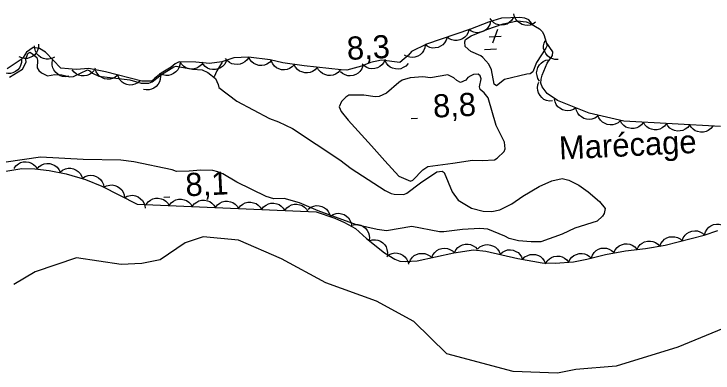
# Model space of a CAD drawing. Extents: x 336540 to 340074, y 5572036 to 5573747.
# Drawn here: x 336751.6 to 336842.2, y 5573514.1 to 5573560.7 of the extents above; entities that cross this region are included whole.
import ezdxf

# ---------------------------------------------------------------- set-up
doc = ezdxf.new("R2010")
doc.units = 0
for name, color, linetype in [('Niveau 2', 7, 'Continuous'), ('Niveau 3', 7, 'Continuous'), ('Niveau 4', 7, 'Continuous'), ('Niveau 44', 7, 'Continuous'), ('Niveau 7', 7, 'Continuous')]:
    doc.layers.add(name, color=color, linetype=linetype)

msp = doc.modelspace()

# ---------------------------------------------------------------- linework, layer by layer
at = {"layer": 'Niveau 2'}
msp.add_lwpolyline([(336844.29, 5573520.18), (336837.67, 5573517.45), (336829.68, 5573514.99), (336824.44, 5573514.55), (336822.1, 5573514.1), (336816.33, 5573514.3), (336807.75, 5573516.58), (336803.46, 5573520.78), (336798.6, 5573523.41), (336792.05, 5573525.78), (336786.31, 5573528.9), (336780.75, 5573531.32), (336776.16, 5573531.76), (336773.82, 5573530.97), (336770.56, 5573528.77), (336768.22, 5573528.3), (336765.51, 5573528.16), (336759.71, 5573529.05), (336754.39, 5573527.24), (336751.62, 5573525.57)], dxfattribs=at)
at = {"layer": 'Niveau 3'}
for p, q in [((336814.31, 5573558.66), (336813.66, 5573556.86)), ((336813.22, 5573557.7), (336814.78, 5573557.78)), ((336812.6, 5573556.07), (336814.19, 5573556.15)), ((336803.13, 5573547.11), (336803.93, 5573547.15)), ((336771.04, 5573536.91), (336771.84, 5573536.95))]:
    msp.add_line(p, q, dxfattribs=at)
at = {"layer": 'Niveau 4'}
for points in [[(336815.2, 5573552.15), (336814.19, 5573551.34), (336813.86, 5573551.56), (336813.54, 5573553.42), (336813.19, 5573554.14), (336812.42, 5573555.02), (336812.13, 5573555.23), (336810.87, 5573555.8), (336810.12, 5573556.44), (336810.05, 5573557.04), (336810.15, 5573557.33), (336810.9, 5573557.82), (336812.91, 5573558.65), (336815.05, 5573559.4), (336816.88, 5573559.76), (336818.03, 5573559.66), (336818.5, 5573559.48), (336819.77, 5573558.74), (336820.08, 5573558.37), (336820.3, 5573557.98), (336820.73, 5573556.56), (336820.59, 5573556.24), (336819.36, 5573554.38), (336818.9, 5573553.15), (336818.55, 5573552.88), (336818.1, 5573552.86), (336815.2, 5573552.15)], [(336751.05, 5573552.48), (336752.75, 5573553.49), (336753.19, 5573554.43), (336753.18, 5573554.78), (336753.4, 5573555.53), (336753.68, 5573555.69), (336754.03, 5573555.51), (336754.59, 5573555.02), (336754.68, 5573554.66), (336754.63, 5573553.68), (336754.86, 5573553.35), (336755.2, 5573553.02), (336755.99, 5573552.63), (336756.91, 5573552.83), (336757.84, 5573552.77), (336758.88, 5573552.49), (336759.36, 5573552.56), (336761.15, 5573553.42), (336761.47, 5573553.28), (336761.82, 5573552.97), (336762.61, 5573552.58), (336766.65, 5573552.1), (336768.12, 5573551.67), (336769.11, 5573551.67), (336769.53, 5573551.87), (336770.75, 5573552.79), (336772.35, 5573553.79), (336772.66, 5573553.88), (336774.77, 5573553.52), (336776.02, 5573553.42), (336776.77, 5573553.06), (336777.75, 5573552.3), (336778.1, 5573551.51), (336778.16, 5573551.11), (336780.53, 5573549.35), (336784.73, 5573547.09), (336785.93, 5573546.67), (336787.73, 5573545.81), (336793.87, 5573541.76), (336795.34, 5573540.62), (336799.75, 5573537.77), (336800.53, 5573537.4), (336800.89, 5573537.31), (336802.15, 5573537.26), (336802.56, 5573537.42), (336804.33, 5573538.76), (336806.42, 5573540.2), (336807.14, 5573540.29), (336807.38, 5573540.1), (336808.42, 5573537.61), (336809.2, 5573536.51), (336810.93, 5573535.47), (336812.43, 5573535.07), (336813.57, 5573535.04), (336814.6, 5573535.28), (336816.16, 5573536.04), (336817.61, 5573537.02), (336819.72, 5573538.28), (336821.34, 5573539.01), (336822.69, 5573539.31), (336823.55, 5573539.09), (336824.86, 5573538.46), (336826.07, 5573537.59), (336827.55, 5573536.36), (336828.25, 5573535.45)], [(336828.25, 5573535.45), (336828.13, 5573534.78), (336827.9, 5573534.43), (336827.21, 5573533.81), (336824.31, 5573532.89), (336822.67, 5573532.11), (336819.92, 5573531.12), (336818.65, 5573531.11), (336817.01, 5573531.26), (336815.81, 5573531.54), (336815.26, 5573531.84), (336813.04, 5573532.77), (336812, 5573532.82), (336809.76, 5573532.72), (336807.37, 5573532.41), (336806.78, 5573532.4), (336803.2, 5573533.11), (336799.93, 5573532.54), (336798.72, 5573532.73), (336796.04, 5573533.33), (336791.04, 5573535.13), (336788.62, 5573536.16), (336786.67, 5573536.72), (336785.31, 5573536.71), (336784.3, 5573536.99), (336780.5, 5573538.85), (336778.69, 5573539.93), (336778.07, 5573540.21), (336777.39, 5573540.37), (336775.85, 5573540.42), (336774.35, 5573540.26), (336772.7, 5573540.25), (336772.12, 5573540.44), (336767.17, 5573541.5), (336765.48, 5573541.69), (336760.58, 5573541.8), (336755.06, 5573542.1), (336750.61, 5573541.46)]]:
    msp.add_lwpolyline(points, dxfattribs=at)
at = {"layer": 'Niveau 44'}
for points in [[(336819.25, 5573559.59), (336818.9, 5573559.35), (336818.52, 5573559.22), (336818.19, 5573559.16), (336817.84, 5573559.2), (336817.49, 5573559.3), (336817.16, 5573559.5), (336816.89, 5573559.69), (336816.69, 5573559.98), (336816.53, 5573560.31), (336816.44, 5573560.66)], [(336818.95, 5573559.19), (336818.38, 5573559.92), (336817.83, 5573560.13), (336817.2, 5573560.19), (336814.82, 5573560.11), (336813.12, 5573559.61), (336810.81, 5573558.71), (336805.11, 5573556.76), (336803.17, 5573555.79), (336802.79, 5573555.33), (336801.65, 5573554.36), (336799.26, 5573554.66), (336797.84, 5573554.38), (336796.66, 5573553.89), (336794.79, 5573553.39), (336794.03, 5573553.4), (336789.24, 5573553.94), (336786.47, 5573554.31), (336784.83, 5573554.7), (336782.02, 5573555.08), (336780.13, 5573554.96), (336778.59, 5573554.47), (336776.95, 5573554.24), (336775.18, 5573554.41), (336773.06, 5573554.45), (336772.53, 5573554.2), (336771.99, 5573553.77), (336770.725, 5573552.987), (336769.821, 5573552.287), (336769.46, 5573551.93), (336768.19, 5573551.93), (336763.47, 5573553.16), (336761.35, 5573553.58), (336759.69, 5573553.44), (336757.72, 5573553.65), (336755.731, 5573555.712), (336754.935, 5573556.163)], [(336813.4, 5573559.72), (336813.31, 5573559.31), (336813.11, 5573558.96), (336812.91, 5573558.7), (336812.62, 5573558.49), (336812.29, 5573558.33), (336811.92, 5573558.25), (336811.59, 5573558.22), (336811.25, 5573558.29), (336810.9, 5573558.43), (336810.61, 5573558.63)], [(336816.35, 5573560.16), (336816.13, 5573559.81), (336815.82, 5573559.54), (336815.54, 5573559.36), (336815.21, 5573559.26), (336814.84, 5573559.21), (336814.46, 5573559.27), (336814.14, 5573559.34), (336813.84, 5573559.53), (336813.56, 5573559.77), (336813.35, 5573560.06)], [(336810.6, 5573558.64), (336810.49, 5573558.24), (336810.28, 5573557.89), (336810.07, 5573557.64), (336809.77, 5573557.44), (336809.43, 5573557.29), (336809.06, 5573557.23), (336808.73, 5573557.21), (336808.39, 5573557.3), (336808.05, 5573557.45), (336807.76, 5573557.67)], [(336807.76, 5573557.67), (336807.65, 5573557.26), (336807.44, 5573556.92), (336807.23, 5573556.67), (336806.93, 5573556.47), (336806.6, 5573556.32), (336806.22, 5573556.26), (336805.89, 5573556.24), (336805.55, 5573556.33), (336805.21, 5573556.48), (336804.93, 5573556.7)], [(336843.22, 5573546.08), (336830.69, 5573546.74), (336826.18, 5573547.81), (336822.07, 5573549.46), (336820.75, 5573550.33), (336820.11, 5573551.2), (336819.94, 5573551.7), (336819.96, 5573552.2), (336820.09, 5573552.72), (336820.74, 5573554.26), (336821.43, 5573555.27), (336821.49, 5573555.75), (336820.63, 5573557)], [(336822.17, 5573554.76), (336821.75, 5573554.75), (336821.36, 5573554.87), (336821.06, 5573555), (336820.8, 5573555.23), (336820.56, 5573555.52), (336820.4, 5573555.87), (336820.29, 5573556.17), (336820.29, 5573556.53), (336820.34, 5573556.89), (336820.47, 5573557.23)], [(336754.935, 5573556.163), (336754.13, 5573556.3), (336753.25, 5573555.72), (336752.82, 5573555.02), (336752.43, 5573554.66), (336750.76, 5573553.55)], [(336754.81, 5573556.75), (336754.81, 5573556.33), (336754.68, 5573555.94), (336754.54, 5573555.65), (336754.31, 5573555.38), (336754.02, 5573555.15), (336753.67, 5573555), (336753.36, 5573554.9), (336753.01, 5573554.9), (336752.64, 5573554.96), (336752.31, 5573555.1)], [(336756.89, 5573555.05), (336756.52, 5573554.87), (336756.12, 5573554.8), (336755.79, 5573554.79), (336755.45, 5573554.88), (336755.11, 5573555.03), (336754.81, 5573555.28), (336754.58, 5573555.51), (336754.42, 5573555.82), (336754.31, 5573556.18), (336754.28, 5573556.53)], [(336804.94, 5573556.67), (336804.88, 5573556.26), (336804.71, 5573555.89), (336804.54, 5573555.61), (336804.27, 5573555.38), (336803.96, 5573555.18), (336803.59, 5573555.07), (336803.27, 5573555.01), (336802.92, 5573555.05), (336802.57, 5573555.15), (336802.25, 5573555.33)], [(336782.05, 5573555.08), (336781.84, 5573554.72), (336781.54, 5573554.45), (336781.27, 5573554.26), (336780.94, 5573554.15), (336780.57, 5573554.09), (336780.19, 5573554.13), (336779.87, 5573554.2), (336779.57, 5573554.37), (336779.28, 5573554.61), (336779.06, 5573554.89)], [(336785.03, 5573554.67), (336784.75, 5573554.36), (336784.4, 5573554.15), (336784.1, 5573554.02), (336783.75, 5573553.97), (336783.38, 5573553.99), (336783.01, 5573554.11), (336782.71, 5573554.24), (336782.45, 5573554.47), (336782.21, 5573554.75), (336782.05, 5573555.08)], [(336752.62, 5573554.78), (336752.61, 5573554.37), (336752.49, 5573553.98), (336752.35, 5573553.68), (336752.12, 5573553.42), (336751.83, 5573553.18), (336751.48, 5573553.03), (336751.17, 5573552.93), (336750.82, 5573552.93), (336750.45, 5573552.99), (336750.12, 5573553.12)], [(336758.74, 5573552.59), (336758.33, 5573552.52), (336757.92, 5573552.57), (336757.6, 5573552.65), (336757.3, 5573552.84), (336757.03, 5573553.08), (336756.81, 5573553.4), (336756.65, 5573553.68), (336756.59, 5573554.03), (336756.58, 5573554.4), (336756.66, 5573554.75)], [(336773.16, 5573554.49), (336773.14, 5573554.08), (336773.01, 5573553.69), (336772.86, 5573553.4), (336772.62, 5573553.14), (336772.32, 5573552.92), (336771.96, 5573552.78), (336771.65, 5573552.69), (336771.3, 5573552.7), (336770.94, 5573552.77), (336770.61, 5573552.91)], [(336776.16, 5573554.39), (336775.92, 5573554.05), (336775.6, 5573553.8), (336775.31, 5573553.63), (336774.97, 5573553.55), (336774.6, 5573553.52), (336774.22, 5573553.6), (336773.91, 5573553.69), (336773.62, 5573553.89), (336773.35, 5573554.15), (336773.16, 5573554.45)], [(336779.13, 5573554.55), (336778.94, 5573554.17), (336778.67, 5573553.87), (336778.41, 5573553.66), (336778.09, 5573553.53), (336777.73, 5573553.44), (336777.34, 5573553.46), (336777.02, 5573553.5), (336776.7, 5573553.65), (336776.4, 5573553.86), (336776.16, 5573554.13)], [(336787.97, 5573554.11), (336787.69, 5573553.8), (336787.34, 5573553.59), (336787.04, 5573553.45), (336786.69, 5573553.41), (336786.32, 5573553.43), (336785.96, 5573553.54), (336785.66, 5573553.67), (336785.39, 5573553.9), (336785.16, 5573554.18), (336784.99, 5573554.51)], [(336799.73, 5573554.75), (336799.56, 5573554.37), (336799.3, 5573554.06), (336799.06, 5573553.83), (336798.74, 5573553.68), (336798.39, 5573553.58), (336798.01, 5573553.56), (336797.68, 5573553.59), (336797.35, 5573553.72), (336797.04, 5573553.92), (336796.78, 5573554.17)], [(336802.71, 5573554.23), (336802.43, 5573553.91), (336802.09, 5573553.7), (336801.79, 5573553.56), (336801.44, 5573553.52), (336801.07, 5573553.53), (336800.7, 5573553.64), (336800.4, 5573553.77), (336800.13, 5573554), (336799.9, 5573554.28), (336799.73, 5573554.6)], [(336819.77, 5573551.96), (336819.54, 5573552.31), (336819.43, 5573552.7), (336819.38, 5573553.03), (336819.43, 5573553.37), (336819.54, 5573553.73), (336819.75, 5573554.05), (336819.95, 5573554.3), (336820.24, 5573554.5), (336820.58, 5573554.65), (336820.94, 5573554.72)], [(336762.17, 5573553.65), (336761.96, 5573553.28), (336761.67, 5573553), (336761.4, 5573552.81), (336761.07, 5573552.69), (336760.71, 5573552.63), (336760.33, 5573552.66), (336760.01, 5573552.72), (336759.7, 5573552.89), (336759.41, 5573553.12), (336759.18, 5573553.4)], [(336765.08, 5573552.74), (336764.76, 5573552.47), (336764.39, 5573552.3), (336764.08, 5573552.2), (336763.72, 5573552.2), (336763.36, 5573552.26), (336763.01, 5573552.42), (336762.73, 5573552.58), (336762.49, 5573552.85), (336762.29, 5573553.16), (336762.17, 5573553.5)], [(336790.95, 5573553.75), (336790.67, 5573553.43), (336790.33, 5573553.21), (336790.03, 5573553.07), (336789.68, 5573553.02), (336789.32, 5573553.03), (336788.95, 5573553.14), (336788.64, 5573553.26), (336788.37, 5573553.48), (336788.13, 5573553.76), (336787.96, 5573554.08)], [(336793.93, 5573553.41), (336793.66, 5573553.09), (336793.31, 5573552.87), (336793.01, 5573552.74), (336792.67, 5573552.68), (336792.3, 5573552.69), (336791.93, 5573552.8), (336791.63, 5573552.92), (336791.36, 5573553.15), (336791.11, 5573553.43), (336790.95, 5573553.75)], [(336796.85, 5573553.94), (336796.72, 5573553.55), (336796.48, 5573553.22), (336796.25, 5573552.98), (336795.94, 5573552.8), (336795.6, 5573552.68), (336795.22, 5573552.64), (336794.89, 5573552.65), (336794.56, 5573552.76), (336794.23, 5573552.93), (336793.96, 5573553.17)], [(336767.98, 5573551.98), (336767.67, 5573551.71), (336767.3, 5573551.54), (336766.98, 5573551.45), (336766.63, 5573551.44), (336766.26, 5573551.51), (336765.91, 5573551.66), (336765.63, 5573551.83), (336765.4, 5573552.09), (336765.2, 5573552.4), (336765.08, 5573552.74)], [(336770.54, 5573552.99), (336770.61, 5573552.58), (336770.57, 5573552.18), (336770.49, 5573551.86), (336770.31, 5573551.56), (336770.07, 5573551.27), (336769.76, 5573551.05), (336769.47, 5573550.9), (336769.13, 5573550.83), (336768.76, 5573550.81), (336768.4, 5573550.88)], [(336821.45, 5573549.38), (336821.03, 5573549.36), (336820.64, 5573549.46), (336820.33, 5573549.59), (336820.06, 5573549.81), (336819.82, 5573550.09), (336819.64, 5573550.43), (336819.53, 5573550.74), (336819.51, 5573551.09), (336819.55, 5573551.46), (336819.67, 5573551.8)], [(336824.48, 5573548.49), (336824.14, 5573548.26), (336823.75, 5573548.14), (336823.42, 5573548.08), (336823.07, 5573548.13), (336822.72, 5573548.23), (336822.39, 5573548.43), (336822.13, 5573548.63), (336821.93, 5573548.92), (336821.78, 5573549.26), (336821.7, 5573549.61)], [(336827.27, 5573547.37), (336826.92, 5573547.14), (336826.53, 5573547.02), (336826.21, 5573546.97), (336825.86, 5573547.01), (336825.5, 5573547.12), (336825.18, 5573547.32), (336824.92, 5573547.51), (336824.72, 5573547.8), (336824.56, 5573548.14), (336824.48, 5573548.49)], [(336830.24, 5573546.85), (336829.93, 5573546.56), (336829.56, 5573546.39), (336829.25, 5573546.29), (336828.9, 5573546.28), (336828.53, 5573546.33), (336828.18, 5573546.48), (336827.9, 5573546.64), (336827.65, 5573546.9), (336827.45, 5573547.2), (336827.32, 5573547.54)], [(336833.22, 5573546.61), (336832.97, 5573546.27), (336832.64, 5573546.03), (336832.35, 5573545.88), (336832.01, 5573545.81), (336831.64, 5573545.79), (336831.26, 5573545.88), (336830.95, 5573545.98), (336830.67, 5573546.19), (336830.41, 5573546.46), (336830.23, 5573546.76)], [(336836.22, 5573546.45), (336835.97, 5573546.12), (336835.64, 5573545.88), (336835.35, 5573545.72), (336835, 5573545.65), (336834.63, 5573545.64), (336834.26, 5573545.72), (336833.95, 5573545.82), (336833.67, 5573546.03), (336833.41, 5573546.3), (336833.22, 5573546.61)], [(336839.21, 5573546.29), (336838.96, 5573545.96), (336838.63, 5573545.72), (336838.34, 5573545.56), (336838, 5573545.49), (336837.63, 5573545.48), (336837.26, 5573545.56), (336836.95, 5573545.67), (336836.66, 5573545.87), (336836.4, 5573546.14), (336836.22, 5573546.45)], [(336842.21, 5573546.13), (336841.96, 5573545.8), (336841.63, 5573545.56), (336841.34, 5573545.4), (336840.99, 5573545.33), (336840.63, 5573545.32), (336840.25, 5573545.4), (336839.94, 5573545.51), (336839.66, 5573545.72), (336839.4, 5573545.98), (336839.21, 5573546.29)], [(336751.64, 5573540.63), (336751.88, 5573540.97), (336752.2, 5573541.22), (336752.48, 5573541.39), (336752.83, 5573541.47), (336753.19, 5573541.5), (336753.57, 5573541.43), (336753.88, 5573541.33), (336754.17, 5573541.13), (336754.44, 5573540.88), (336754.64, 5573540.57)], [(336750.33, 5573540.25), (336752.63, 5573540.61), (336754.34, 5573540.58), (336756.2, 5573540.36), (336758.41, 5573539.92), (336760.89, 5573539.21), (336763.02, 5573538.31), (336767.6, 5573536)], [(336754.64, 5573540.54), (336754.91, 5573540.86), (336755.25, 5573541.08), (336755.55, 5573541.22), (336755.9, 5573541.27), (336756.27, 5573541.25), (336756.64, 5573541.15), (336756.94, 5573541.02), (336757.21, 5573540.79), (336757.45, 5573540.51), (336757.62, 5573540.19)], [(336757.61, 5573540.15), (336757.93, 5573540.42), (336758.31, 5573540.58), (336758.63, 5573540.66), (336758.98, 5573540.66), (336759.34, 5573540.59), (336759.69, 5573540.42), (336759.96, 5573540.25), (336760.19, 5573539.98), (336760.39, 5573539.66), (336760.5, 5573539.32)], [(336760.51, 5573539.37), (336760.86, 5573539.6), (336761.26, 5573539.71), (336761.58, 5573539.76), (336761.93, 5573539.71), (336762.28, 5573539.59), (336762.6, 5573539.39), (336762.86, 5573539.19), (336763.06, 5573538.89), (336763.21, 5573538.55), (336763.28, 5573538.2)], [(336763.27, 5573538.18), (336763.63, 5573538.39), (336764.03, 5573538.47), (336764.36, 5573538.5), (336764.71, 5573538.43), (336765.05, 5573538.29), (336765.36, 5573538.06), (336765.6, 5573537.84), (336765.77, 5573537.54), (336765.9, 5573537.19), (336765.95, 5573536.83)], [(336765.95, 5573536.83), (336766.31, 5573537.04), (336766.71, 5573537.12), (336767.04, 5573537.15), (336767.38, 5573537.08), (336767.73, 5573536.94), (336768.04, 5573536.71), (336768.28, 5573536.49), (336768.45, 5573536.19), (336768.58, 5573535.84), (336768.63, 5573535.48)], [(336767.6, 5573536), (336790.786, 5573535.001), (336793.231, 5573534.185), (336794.479, 5573533.637), (336795.89, 5573532.86), (336797.31, 5573531.54), (336799.65, 5573529.68), (336800.99, 5573528.86), (336801.66, 5573528.62), (336802.38, 5573528.55), (336803.91, 5573528.63), (336808.63, 5573529.67), (336811.19, 5573530.06), (336812.81, 5573529.92), (336816.95, 5573528.97), (336820.11, 5573528.39), (336821.79, 5573528.36), (336824.14, 5573528.54), (336825.87, 5573528.85), (336828.31, 5573529.49), (336830.88, 5573529.95), (336833.49, 5573530.25), (336836.04, 5573530.68), (336841.1, 5573531.98), (336842.85, 5573532.57)], [(336768.75, 5573535.95), (336769, 5573536.29), (336769.32, 5573536.53), (336769.61, 5573536.69), (336769.96, 5573536.76), (336770.33, 5573536.78), (336770.7, 5573536.7), (336771.01, 5573536.6), (336771.3, 5573536.39), (336771.56, 5573536.13), (336771.75, 5573535.82)], [(336771.75, 5573535.82), (336772, 5573536.16), (336772.32, 5573536.4), (336772.61, 5573536.56), (336772.95, 5573536.63), (336773.32, 5573536.65), (336773.7, 5573536.57), (336774.01, 5573536.47), (336774.29, 5573536.26), (336774.55, 5573536), (336774.74, 5573535.69)], [(336774.74, 5573535.69), (336774.99, 5573536.03), (336775.32, 5573536.27), (336775.61, 5573536.43), (336775.95, 5573536.5), (336776.32, 5573536.52), (336776.7, 5573536.44), (336777.01, 5573536.34), (336777.29, 5573536.13), (336777.55, 5573535.87), (336777.74, 5573535.56)], [(336777.74, 5573535.56), (336777.99, 5573535.9), (336778.32, 5573536.14), (336778.61, 5573536.3), (336778.95, 5573536.38), (336779.32, 5573536.39), (336779.69, 5573536.31), (336780, 5573536.21), (336780.29, 5573536), (336780.55, 5573535.74), (336780.74, 5573535.43)], [(336780.74, 5573535.43), (336780.99, 5573535.77), (336781.31, 5573536.01), (336781.6, 5573536.17), (336781.95, 5573536.25), (336782.32, 5573536.26), (336782.69, 5573536.18), (336783, 5573536.08), (336783.29, 5573535.87), (336783.55, 5573535.61), (336783.74, 5573535.3)], [(336783.74, 5573535.3), (336783.98, 5573535.64), (336784.31, 5573535.88), (336784.6, 5573536.04), (336784.94, 5573536.12), (336785.31, 5573536.13), (336785.69, 5573536.05), (336786, 5573535.95), (336786.28, 5573535.75), (336786.54, 5573535.48), (336786.73, 5573535.18)], [(336786.73, 5573535.18), (336786.98, 5573535.51), (336787.31, 5573535.75), (336787.6, 5573535.91), (336787.94, 5573535.99), (336788.31, 5573536), (336788.68, 5573535.92), (336788.99, 5573535.82), (336789.28, 5573535.62), (336789.54, 5573535.35), (336789.73, 5573535.05)], [(336789.78, 5573535.34), (336790.11, 5573535.59), (336790.5, 5573535.73), (336790.82, 5573535.81), (336791.17, 5573535.78), (336791.53, 5573535.7), (336791.87, 5573535.52), (336792.14, 5573535.33), (336792.35, 5573535.06), (336792.53, 5573534.73), (336792.63, 5573534.39)], [(336792.65, 5573534.44), (336793, 5573534.66), (336793.4, 5573534.77), (336793.72, 5573534.81), (336794.07, 5573534.76), (336794.42, 5573534.64), (336794.74, 5573534.43), (336794.99, 5573534.22), (336795.18, 5573533.93), (336795.33, 5573533.59), (336795.4, 5573533.23)], [(336795.44, 5573533.27), (336795.85, 5573533.37), (336796.26, 5573533.34), (336796.58, 5573533.27), (336796.89, 5573533.11), (336797.18, 5573532.88), (336797.42, 5573532.58), (336797.59, 5573532.3), (336797.67, 5573531.96), (336797.7, 5573531.59), (336797.64, 5573531.23)], [(336841.15, 5573532), (336841.26, 5573532.4), (336841.48, 5573532.74), (336841.69, 5573533), (336841.98, 5573533.19), (336842.32, 5573533.34), (336842.7, 5573533.4), (336843.03, 5573533.41), (336843.37, 5573533.32), (336843.7, 5573533.17), (336843.99, 5573532.95)], [(336838.24, 5573531.25), (336838.38, 5573531.64), (336838.63, 5573531.97), (336838.86, 5573532.2), (336839.16, 5573532.37), (336839.51, 5573532.5), (336839.89, 5573532.53), (336840.22, 5573532.52), (336840.55, 5573532.41), (336840.88, 5573532.23), (336841.15, 5573531.99)], [(336835.34, 5573530.5), (336835.48, 5573530.89), (336835.72, 5573531.22), (336835.95, 5573531.46), (336836.26, 5573531.63), (336836.61, 5573531.75), (336836.99, 5573531.78), (336837.31, 5573531.78), (336837.65, 5573531.66), (336837.97, 5573531.48), (336838.24, 5573531.25)], [(336797.66, 5573531.26), (336798.06, 5573531.38), (336798.47, 5573531.39), (336798.8, 5573531.35), (336799.12, 5573531.21), (336799.43, 5573531), (336799.68, 5573530.72), (336799.87, 5573530.45), (336799.98, 5573530.12), (336800.04, 5573529.75), (336800.01, 5573529.39)], [(336808.72, 5573529.68), (336808.9, 5573530.06), (336809.17, 5573530.36), (336809.43, 5573530.57), (336809.75, 5573530.71), (336810.11, 5573530.8), (336810.49, 5573530.8), (336810.82, 5573530.76), (336811.14, 5573530.61), (336811.44, 5573530.4), (336811.69, 5573530.14)], [(336811.71, 5573530.17), (336812.02, 5573530.46), (336812.39, 5573530.64), (336812.7, 5573530.74), (336813.05, 5573530.75), (336813.42, 5573530.7), (336813.77, 5573530.55), (336814.06, 5573530.4), (336814.3, 5573530.14), (336814.51, 5573529.84), (336814.64, 5573529.5)], [(336829.39, 5573529.68), (336829.56, 5573530.07), (336829.83, 5573530.37), (336830.07, 5573530.59), (336830.39, 5573530.74), (336830.75, 5573530.84), (336831.13, 5573530.84), (336831.46, 5573530.81), (336831.78, 5573530.67), (336832.09, 5573530.47), (336832.34, 5573530.21)], [(336832.37, 5573530.06), (336832.54, 5573530.44), (336832.81, 5573530.75), (336833.06, 5573530.96), (336833.38, 5573531.11), (336833.74, 5573531.2), (336834.12, 5573531.2), (336834.44, 5573531.17), (336834.77, 5573531.02), (336835.08, 5573530.82), (336835.32, 5573530.56)], [(336799.95, 5573529.23), (336800.28, 5573529.48), (336800.67, 5573529.61), (336800.99, 5573529.68), (336801.34, 5573529.65), (336801.7, 5573529.56), (336802.03, 5573529.37), (336802.3, 5573529.18), (336802.51, 5573528.9), (336802.68, 5573528.57), (336802.77, 5573528.22)], [(336805.79, 5573529.04), (336805.94, 5573529.43), (336806.2, 5573529.75), (336806.44, 5573529.98), (336806.75, 5573530.14), (336807.1, 5573530.25), (336807.48, 5573530.27), (336807.81, 5573530.25), (336808.14, 5573530.12), (336808.46, 5573529.94), (336808.72, 5573529.69)], [(336814.64, 5573529.5), (336814.94, 5573529.79), (336815.31, 5573529.96), (336815.62, 5573530.07), (336815.97, 5573530.08), (336816.34, 5573530.03), (336816.69, 5573529.88), (336816.98, 5573529.73), (336817.22, 5573529.47), (336817.43, 5573529.16), (336817.56, 5573528.83)], [(336826.47, 5573529.01), (336826.61, 5573529.4), (336826.85, 5573529.73), (336827.08, 5573529.97), (336827.39, 5573530.14), (336827.73, 5573530.27), (336828.12, 5573530.3), (336828.44, 5573530.29), (336828.77, 5573530.18), (336829.1, 5573530.01), (336829.37, 5573529.77)], [(336802.86, 5573528.4), (336803.01, 5573528.79), (336803.27, 5573529.11), (336803.51, 5573529.33), (336803.82, 5573529.49), (336804.17, 5573529.61), (336804.55, 5573529.62), (336804.88, 5573529.61), (336805.21, 5573529.48), (336805.53, 5573529.29), (336805.79, 5573529.04)], [(336817.57, 5573528.86), (336817.86, 5573529.15), (336818.22, 5573529.35), (336818.53, 5573529.47), (336818.88, 5573529.49), (336819.25, 5573529.46), (336819.61, 5573529.33), (336819.9, 5573529.19), (336820.15, 5573528.94), (336820.37, 5573528.64), (336820.52, 5573528.31)], [(336820.53, 5573528.26), (336820.74, 5573528.63), (336821.03, 5573528.91), (336821.3, 5573529.1), (336821.63, 5573529.21), (336822, 5573529.27), (336822.38, 5573529.24), (336822.7, 5573529.18), (336823.01, 5573529), (336823.3, 5573528.77), (336823.52, 5573528.49)], [(336823.53, 5573528.43), (336823.7, 5573528.81), (336823.96, 5573529.12), (336824.21, 5573529.34), (336824.53, 5573529.49), (336824.89, 5573529.58), (336825.27, 5573529.59), (336825.59, 5573529.56), (336825.92, 5573529.42), (336826.23, 5573529.22), (336826.48, 5573528.96)]]:
    msp.add_lwpolyline(points, dxfattribs=at)
at = {"layer": 'Niveau 7'}
for points in [[(336778.63, 5573554.42), (336777.94, 5573553.3), (336777.57, 5573552.49)], [(336808.52, 5573541.33), (336811.08, 5573541.72), (336812.31, 5573541.66), (336813.9, 5573541.75), (336814.25, 5573541.95), (336815.16, 5573542.82), (336815.31, 5573543.19), (336815.23, 5573544.02), (336814.12, 5573546.21), (336813.1, 5573549.8), (336812.56, 5573550.44), (336812.04, 5573550.86), (336811.97, 5573551.22), (336812.21, 5573552.25), (336812.06, 5573552.63), (336811.8, 5573552.87), (336811.19, 5573552.79), (336810.83, 5573552.66), (336810.48, 5573552.43), (336810.2, 5573552.09), (336809.52, 5573551.78), (336809.05, 5573552.02), (336808.66, 5573552.4), (336807.85, 5573552.75), (336805.62, 5573552.38), (336804.62, 5573552.49), (336802.97, 5573552.4), (336801.95, 5573552.06), (336801.53, 5573551.79), (336799.91, 5573550.41), (336798.97, 5573549.98), (336798.46, 5573549.91), (336796.97, 5573550.11), (336795.05, 5573550.11), (336794.65, 5573549.88), (336794.08, 5573549.32), (336793.8, 5573548.64), (336794.02, 5573548.03), (336794.94, 5573546.9), (336797.99, 5573543.57), (336799.68, 5573541.6), (336801.53, 5573539.64), (336803.04, 5573538.96), (336803.31, 5573539.12), (336804.63, 5573540.47), (336805.27, 5573540.89), (336808.52, 5573541.33)]]:
    msp.add_lwpolyline(points, dxfattribs=at)

# ---------------------------------------------------------------- texts
at = {"layer": 'Niveau 3'}
for s, p in [('    8,3 ', (336790.39, 5573554.48)), ('8,8    ', (336806.01, 5573547.21)), ('8,1    ', (336773.92, 5573537.01))]:
    msp.add_text(s, height=3, rotation=2.7712, dxfattribs=at).set_placement(p)
at = {"layer": 'Niveau 7'}
msp.add_text('Marécage', height=3, rotation=2.77808, dxfattribs=at).set_placement((336822.35, 5573541.78))

doc.saveas('drawing.dxf')
